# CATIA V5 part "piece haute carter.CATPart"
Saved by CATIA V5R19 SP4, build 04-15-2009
Part number: piece droite carter
Material "Plastique brillant": density 1200 kg/m3, Young's modulus 2.2e+09 Pa, Poisson ratio 0.38, thermal expansion 6.84e-05 1/K
Bounding box of the stored display mesh (mm): x 0 to 17.7, y -143.505 to 592.858, z -82.118 to 132.474
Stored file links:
  G:\EU_thinkMotion\CFAO_2010\MMS_groupe1\MMS_groupe1\A reprendre\OK\rdeneffle\piece haute carter.CATPart
  C:\Program Files\Dassault Systemes\B19\intel_a\startup\materials\French\Catalog.CATMaterial
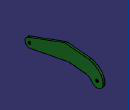
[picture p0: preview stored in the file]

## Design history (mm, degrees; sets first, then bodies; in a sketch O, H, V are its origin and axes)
Body1 (main body), material "Plastique brillant"
  Sketch1 on yz-plane, origin (0, 0, 0), H (0, 1, 0), V (0, 0, 1)
    line L1 (-115.8569, 5.5867) -> (231.1101, 133.3715)
    line L2 (-92.9007, -75.9825) -> (265.6157, -4.8754)
    arc A1 centre (-101.169, -34.2945) radius 42.5 from (-115.8569, 5.5867) to (-92.9007, -75.9825) ccw
    point P5 (-101.169, -34.2945)
    line L3 (231.1101, 133.3715) -> (463.899, 112.1961)
    point P6 (463.899, 112.1961)
    line L4 (265.6157, -4.8754) -> (417.9866, -18.7357)
    point P7 (417.9866, -18.7357)
    point P8 (535.8579, -25.2291)
    point P9 (498.4495, -68.2362)
    point P10 (573.2442, 17.7972)
    spline S1 through (463.899, 112.1961) (517.8359, 90.8537) (573.2442, 39.8908) (592.8579, -25.2291)
    spline S2 through (417.9866, -18.7357) (442.583, -22.9106) (473.0665, -41.2867) (498.4495, -68.2362) (498.4495, -68.2362)
    arc A2 centre (535.8579, -25.2291) radius 57 from (498.4495, -68.2362) to (592.8579, -25.2291) ccw
    point P12 (592.8579, -25.2291)
    point P13 (463.899, 112.1961)
    point P14 (592.8579, -25.2291)
    point P15 (417.9866, -18.7357)
    point P19 (498.4495, -68.2362)
    radius A1 = 42.5
    length L2 = 365.5
    angle L1 L2 = 9
    length L1 = 369.75
    length L3 = 233.75
    length L4 = 153
    distance P8 P6 = 155.125
    distance P7 P8 = 118.05
    radius A2 = 57
    distance P8 P5 = 637.0914
    distance P5 H = 34.2945
    distance H P8 = 25.2291
    tangency: A1 L1, L2 A1
    parallelism: L4 L3
    coincidence: P13 P6, P15 P7, P19 P9, A2 P10, P14 P12
  Pad1: profile Sketch1, direction (1, 0, 0), length 17.7
  Fillet1: radius 50, on edge [face of Pad1 from Sketch1.L1 | face of Pad1 from Sketch1.L3]
  Fillet2: radius 50, on edge [face of Pad1 from Sketch1.L4 | face of Pad1 from Sketch1.L2]
  Sketch2 on end face of Pad1, origin (17.7, 0, 0), H (0, 1, 0), V (0, 0, 1)
    circle A1 centre (535.8579, -25.2291) radius 13
    circle A2 centre (-101.169, -34.2945) radius 13
    reference projected arc E1 centre (-101.169, -34.2945) radius 42.5 from (-115.8569, 5.5867) to (-92.9007, -75.9825) ccw from edge [face of Pad1 from Sketch1.A1 | end face of Pad1]
    reference projected arc E2 centre (535.8579, -25.2291) radius 57 from (498.4495, -68.2362) to (592.8579, -25.2291) ccw from edge [face of Pad1 from Sketch1.A2 | end face of Pad1]
    radius A2 = 13
    radius A1 = 13
    concentricity: A2 E1, A1 E2
  Pocket1: profile Sketch2, direction (-1, 0, 0), length 17.7
  Sketch3 on start face of Pad1, origin (0, 0, 0), H (0, -1, 0), V (0, 0, 1)
    circle A1 centre (-535.8579, -25.2291) radius 24
    reference projected circle E1 centre (-535.8579, -25.2291) radius 13 from edge [face of Pocket1 from Sketch2.A1 | start face of Pad1]
    radius A1 = 24
    concentricity: A1 E1
  Pocket2: profile Sketch3, direction (1, 0, 0), length 13
  DatumCurve1
  Sketch4 on end face of Pad1, origin (17.7, 0, 0), H (0, 1, 0), V (0, 0, 1)
    circle A1 centre (-101.1686, -34.2957) radius 24
    reference projected point E1 (-101.1686, -34.2957) from edge of DatumCurve1
    radius A1 = 24
    concentricity: A1 E1
  Pocket3: profile Sketch4, direction (1, 0, 0), length 13
  DatumCurve2
  Sketch5 on face of Pocket3, origin (17.7, 0, 0), H (0, 1, 0), V (0, 0, 1)
    circle A1 centre (-101.1686, -34.2957) radius 23.5
    reference projected circle E1 centre (-101.1686, -34.2957) radius 43 from edge of DatumCurve2
    radius A1 = 23.5
    concentricity: A1 E1
  Pocket4: profile Sketch5, direction (1, 0, 0), length 13
  DatumCurve3
  Sketch6 on start face of Pad1, origin (0, 0, 0), H (0, -1, 0), V (0, 0, 1)
    circle A1 centre (101.169, -34.2945) radius 23.5
    reference projected arc E1 centre (101.169, -34.2945) radius 42.5 from (92.9007, -75.9825) to (115.8569, 5.5867) ccw from edge [start face of Pad1 | face of Pad1 from Sketch1.A1]
    radius A1 = 23.5
    concentricity: A1 E1
  Pocket5: profile Sketch6, direction (1, 0, 0), length 13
